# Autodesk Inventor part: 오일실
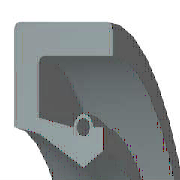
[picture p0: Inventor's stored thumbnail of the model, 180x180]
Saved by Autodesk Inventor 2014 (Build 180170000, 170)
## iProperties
IsCustomPart: 1
Created: 2015-12
Part Number: 오일실
Material: 고무
Description: 오일-실
Document SubType Name: Modeling
Standard: KS B 2804
Designer: mdu
Standards Organization: KS
Language: ko-KR
Size Designation: S - 15 30 7
Categories: <MemberInstance><Categories><Category DisplayName="샤프트 부품" InternalName="7f7aeb1f-a693-4053-b835-cee3144e0d98" Mnemonic="SHFT"><Category DisplayName="실링" Intern
Density: 1 g/cm^3
Appearance: 고무 - 검은색 - 버전 1.1
Author: mdu
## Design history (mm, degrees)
revolve "본체" stored, may be unused: angle "d17" = 90 deg
revolve "스프링1" stored, may be unused: angle "d18" = 90 deg
body "Solid1"
sketch "스케치1"
  geometry: L1 (0, 15)-(7, 15); L2 (7, 15)-(7, 13.75); L3 (7, 13.75)-(1.75, 13.75); L4 (0, 15)-(0, 9.6); L5 (0, 9.6)-(1.75, 9.25); L6 (1.75, 9.25)-(4.9, 7.5); L7 (4.9, 7.5)-(0, 7.5); L8 (6.3, 8.375)-(6.3, 9.6); L9 (0, 0)-(9.586, 0) reference; L10 (4.9, 7.5)-(6.3, 8.375); L11 (0, 18)-(0, -3) reference; L12 (-1.917, 0)-(11.503, 0) reference; L13 (4.2, 9.6)-(1.75, 10.09); L14 (1.75, 10.09)-(1.75, 13.75); L15 (6.3, 9.6)-(5.6, 9.6); C1 r 0.455 at (4.9, 9.6); A1 r 0.7 centre (4.9, 9.6) between (5.6, 9.6) and (4.2, 9.6)
  constraints: 26 end point, 5 horizontal alignment, 4 perpendicular, 2 centre point, 2 collinear, 2 horizontal, 2 parallel, 2 point on circle, 2 point on line, 2 vertical alignment, 1 coincident
  dimensions: "d0" = 30 diameter of L1 L9 (= SD2); "d1" = 16.75 diameter of L8.start L9 (= ABDM); "d2" = 1.25 distance of L1.end L2.end (computed from SD); "d3" = 0.91 diameter of C1 (= SPDI); "d4" = 1.4 diameter of A1 (= SPDA); "d5" = 15 diameter of L6.end L9 (= NND); "d6" = 18.5 diameter of L5.end L9 (= TKDM); "d7" = 19.2 diameter of L4.end L9 (= HLDM); "d8" = 4.9 distance from line of C1.centre L4 (= SPDST); "d9" = 6.3 distance between parallel lines of L8 L4 (= SDI); "d10" = 7 distance between parallel lines of L2 L4 (= SWDT); "d12" = 1.75 distance between parallel lines of L14 L4 (= SD)
fillet "모깎기1" dims "d11" = 0.3 (= RR)
other parameters: "SD2" = 30 [user parameter; used in 1 equation term], "SWDT" = 7 [user parameter; used in 1 equation term], "RR" = 0.3 [user parameter; used in 1 equation term], "SD" = 1.75 [user parameter; used in 2 equation terms], "NND" = 15 [user parameter; used in 1 equation term], "SPDA" = 1.4 [user parameter; used in 1 equation term], "SPDI" = 0.91 [user parameter; used in 1 equation term], "TKDM" = 18.5 [user parameter; used in 1 equation term], "HLDM" = 19.2 [user parameter; used in 1 equation term], "ABDM" = 16.75 [user parameter; used in 1 equation term], "SDI" = 6.3 [user parameter; used in 1 equation term], "SPDST" = 4.9 [user parameter; used in 1 equation term], "d13" = 0, "d14" = 0, "d15" = 0, "LAB" = 0.35 [user parameter]
